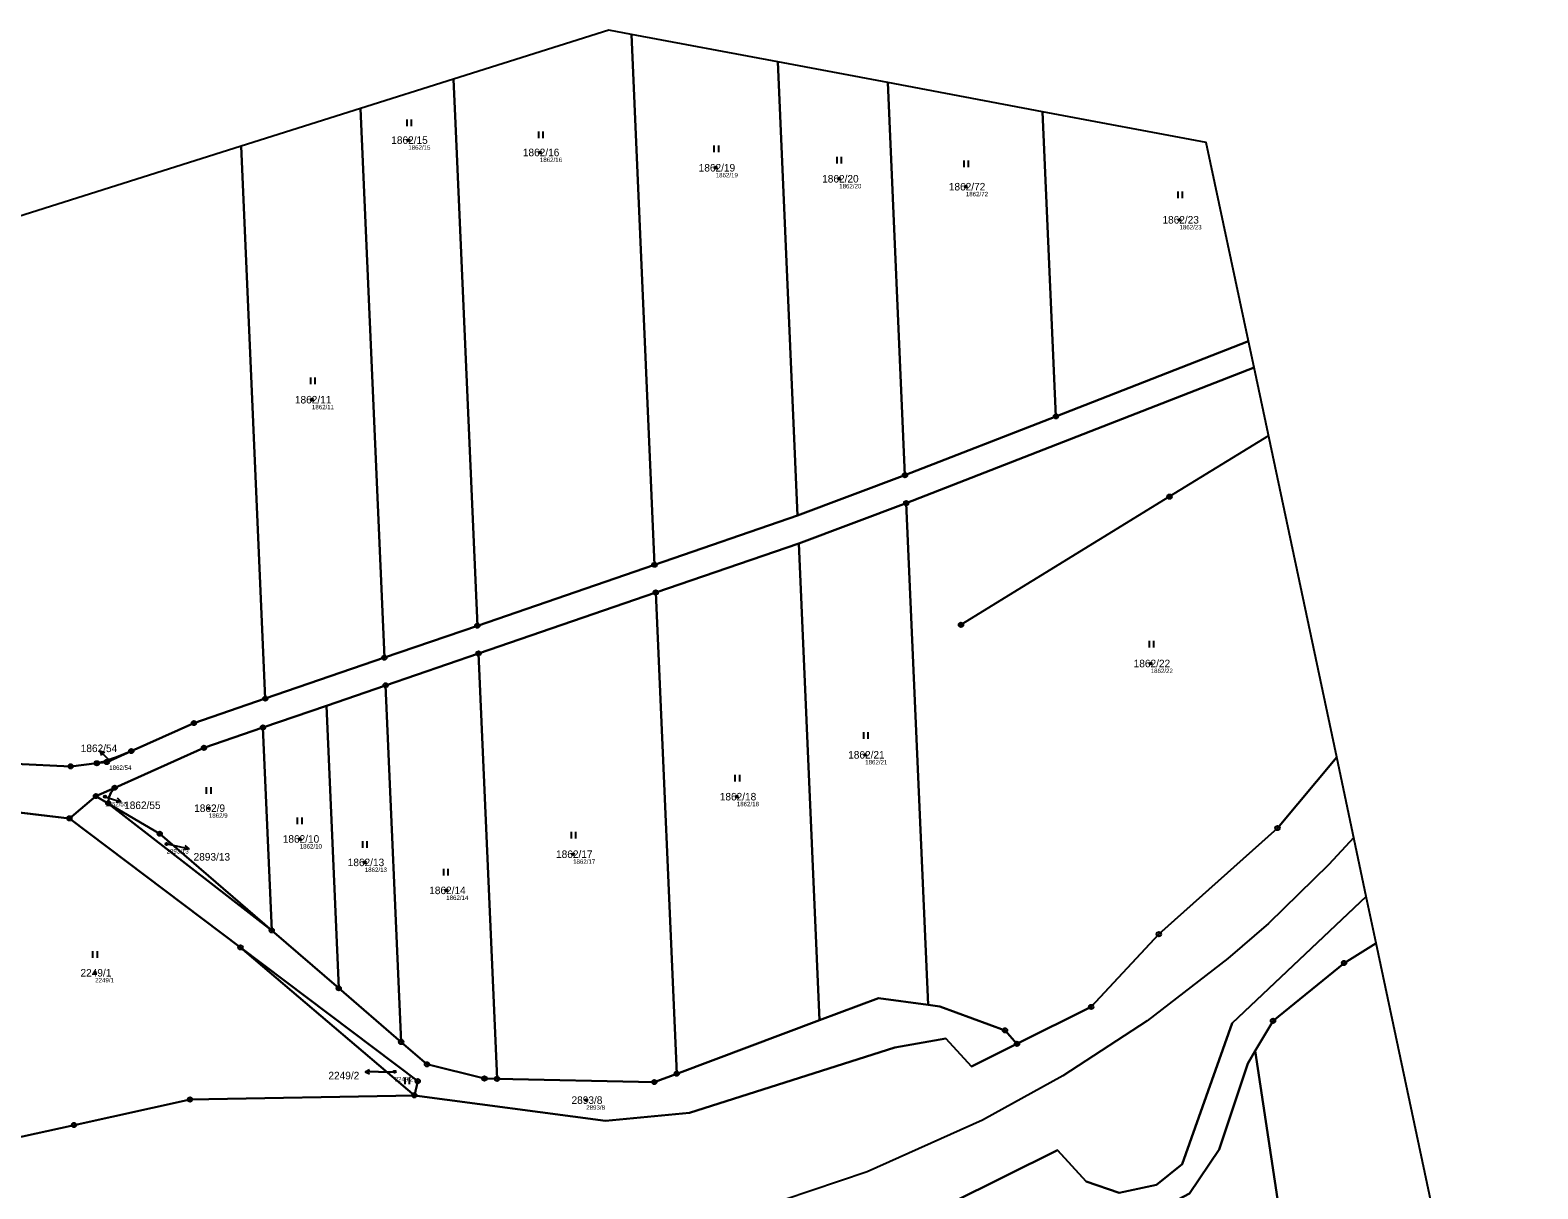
# Model space of a CAD drawing. Extents: x -758777 to -757896, y -1175225 to -1174486.
# Drawn here: x -758235.7 to -757895.9, y -1174746.8 to -1174485.6 of the extents above; entities that cross this region are included whole.
import ezdxf

# ---------------------------------------------------------------- set-up
doc = ezdxf.new("R2010")
doc.units = 0
for name, color, linetype in [('Definiční body', 7, 'Continuous'), ('Hranice parcel', 7, 'Continuous'), ('Parcelní čísla', 7, 'Continuous'), ('Polygon parcely', 7, 'Continuous'), ('Pop  PČ popisy', 7, 'Continuous'), ('Poz předměty', 7, 'Continuous'), ('Značky bodu BP', 7, 'Continuous'), ('Značky kultur', 7, 'Continuous')]:
    doc.layers.add(name, color=color, linetype=linetype)

msp = doc.modelspace()

# ---------------------------------------------------------------- linework, layer by layer
at = {"layer": 'Definiční body'}
for centre in [(-758150.45, -1174510.36), (-758120.8, -1174513.14), (-758081.18, -1174516.59), (-758053.36, -1174519.07), (-758024.82, -1174520.86), (-757976.69, -1174528.32), (-758172.16, -1174568.87), (-757983.17, -1174628.33), (-758217.83, -1174650.15), (-758047.5, -1174648.92), (-758218.78, -1174658.37), (-758076.43, -1174658.35), (-758195.39, -1174660.95), (-758174.9, -1174667.88), (-758204.92, -1174669.01), (-758113.32, -1174671.32), (-758160.26, -1174673.16), (-758141.9, -1174679.47), (-758221, -1174698.05), (-758153.53, -1174720.36), (-758110.36, -1174726.75)]:
    msp.add_circle(centre, 0.25, dxfattribs=at)
at = {"layer": 'Hranice parcel'}
for p, q in [((-758094.97, -1174606.08), (-758100.17, -1174486.52)), ((-758067.2, -1174492.73), (-758062.75, -1174595)), ((-758038.54, -1174585.88), (-758042.38, -1174497.4)), ((-758155.84, -1174627.01), (-758161.23, -1174503.26)), ((-758007.52, -1174503.96), (-758004.53, -1174572.62)), ((-758182.68, -1174636.24), (-758188.1, -1174511.75)), ((-757961.14, -1174555.7), (-758004.53, -1174572.62)), ((-758038.26, -1174592.18), (-757959.89, -1174561.63)), ((-758004.53, -1174572.62), (-758038.54, -1174585.88)), ((-758038.54, -1174585.88), (-758062.75, -1174595)), ((-758062.47, -1174601.25), (-758038.26, -1174592.18)), ((-758038.26, -1174592.18), (-758033.33, -1174705.3)), ((-758062.75, -1174595), (-758094.97, -1174606.08)), ((-758094.69, -1174612.33), (-758062.47, -1174601.25)), ((-758062.47, -1174601.25), (-758057.8, -1174708.75)), ((-758094.97, -1174606.08), (-758134.89, -1174619.81)), ((-758134.62, -1174626.06), (-758094.69, -1174612.33)), ((-758089.97, -1174720.79), (-758094.69, -1174612.33)), ((-758134.89, -1174619.81), (-758155.84, -1174627.01)), ((-758155.84, -1174627.01), (-758182.68, -1174636.24)), ((-758155.57, -1174633.26), (-758134.62, -1174626.06)), ((-758134.62, -1174626.06), (-758130.45, -1174721.94)), ((-758168.89, -1174637.84), (-758155.57, -1174633.26)), ((-758152.07, -1174713.65), (-758155.57, -1174633.26)), ((-758183.21, -1174642.76), (-758168.89, -1174637.84)), ((-758168.89, -1174637.84), (-758166.12, -1174701.53)), ((-758181.22, -1174688.49), (-758183.21, -1174642.76)), ((-758226.78, -1174663.24), (-758220.83, -1174658.22)), ((-758220.83, -1174658.22), (-758216.61, -1174656.33)), ((-758218.05, -1174659.86), (-758220.83, -1174658.22)), ((-758254.5, -1174659.99), (-758226.78, -1174663.24)), ((-758181.22, -1174688.49), (-758218.05, -1174659.86)), ((-758226.78, -1174663.24), (-758188.26, -1174692.33)), ((-758166.12, -1174701.53), (-758181.22, -1174688.49)), ((-758149.09, -1174725.67), (-758188.26, -1174692.33)), ((-758166.12, -1174701.53), (-758152.07, -1174713.65)), ((-758089.97, -1174720.79), (-758057.8, -1174708.75))]:
    msp.add_line(p, q, dxfattribs=at)
for points in [[(-758134.89, -1174619.81), (-758139.82, -1174506.61), (-758140.25, -1174496.64)], [(-758212.86, -1174648.07), (-758198.75, -1174641.76), (-758182.68, -1174636.24)], [(-758216.61, -1174656.33), (-758196.5, -1174647.34), (-758183.21, -1174642.76)], [(-758220.63, -1174650.81), (-758219.98, -1174650.66), (-758219, -1174650.41), (-758218.05, -1174650.11), (-758217.1, -1174649.77), (-758216.19, -1174649.41), (-758212.86, -1174648.07)], [(-758212.86, -1174648.07), (-758218.37, -1174650.54), (-758220.63, -1174650.81)], [(-758239.06, -1174650.93), (-758226.51, -1174651.52), (-758220.63, -1174650.81)], [(-758013.3, -1174714.07), (-757996.59, -1174705.74), (-757981.33, -1174689.35), (-757954.6, -1174665.43), (-757941.27, -1174649.42)], [(-758216.61, -1174656.33), (-758216.89, -1174656.64), (-758217.45, -1174657.45), (-758217.83, -1174658.36), (-758218.03, -1174659.32), (-758218.05, -1174659.86)], [(-758218.05, -1174659.86), (-758206.46, -1174666.7), (-758181.22, -1174688.49)], [(-757934.61, -1174680.85), (-757964.85, -1174709.42), (-757976.05, -1174741.17), (-757981.89, -1174745.86), (-757990.29, -1174747.68), (-757997.69, -1174745.08), (-758004.14, -1174738), (-758040.32, -1174755.99), (-758089.84, -1174768.68), (-758142.71, -1174770.26), (-758184.87, -1174772.83)], [(-757959.61, -1174715.65), (-757955.61, -1174708.87), (-757939.6, -1174695.85), (-757932.38, -1174691.39)], [(-758188.26, -1174692.33), (-758148.33, -1174722.48), (-758149.09, -1174725.67)], [(-758057.8, -1174708.75), (-758044.51, -1174703.78), (-758033.33, -1174705.3)], [(-758033.33, -1174705.3), (-758030.68, -1174705.66), (-758016, -1174711.02), (-758013.3, -1174714.07)], [(-758152.07, -1174713.65), (-758146.25, -1174718.68), (-758133.29, -1174721.88), (-758130.45, -1174721.94)], [(-758149.09, -1174725.67), (-758106.02, -1174731.44), (-758087.1, -1174729.64), (-758040.84, -1174714.91), (-758029.32, -1174712.86), (-758023.54, -1174719.17), (-758013.3, -1174714.07)], [(-757991.64, -1174752.6), (-757980.81, -1174751.2), (-757974.41, -1174747.76), (-757967.73, -1174737.89), (-757961.29, -1174718.5), (-757959.61, -1174715.65)], [(-757959.61, -1174715.65), (-757943.53, -1174822.15), (-757927.46, -1174928.58)], [(-758130.45, -1174721.94), (-758095.02, -1174722.68), (-758089.97, -1174720.79)], [(-758149.09, -1174725.67), (-758199.62, -1174726.6), (-758225.76, -1174732.36), (-758252.17, -1174738.18), (-758254.97, -1174739.34)]]:
    msp.add_lwpolyline(points, dxfattribs=at)
at = {"layer": 'Polygon parcely'}
for p, q in [((-758067.2, -1174492.73), (-758100.17, -1174486.52)), ((-758042.38, -1174497.4), (-758067.2, -1174492.73)), ((-758140.25, -1174496.64), (-758161.23, -1174503.26)), ((-758007.52, -1174503.96), (-758042.38, -1174497.4)), ((-758161.23, -1174503.26), (-758188.1, -1174511.75)), ((-757959.89, -1174561.63), (-757961.14, -1174555.7)), ((-757941.27, -1174649.42), (-757959.89, -1174561.63)), ((-757934.61, -1174680.85), (-757941.27, -1174649.42)), ((-757932.38, -1174691.39), (-757934.61, -1174680.85))]:
    msp.add_line(p, q, dxfattribs=at)
for points in [[(-758100.17, -1174486.52), (-758105.23, -1174485.57), (-758140.25, -1174496.64)], [(-758140.25, -1174496.64), (-758139.82, -1174506.61), (-758134.89, -1174619.81), (-758094.97, -1174606.08), (-758100.17, -1174486.52)], [(-758100.17, -1174486.52), (-758094.97, -1174606.08), (-758062.75, -1174595), (-758067.2, -1174492.73)], [(-758067.2, -1174492.73), (-758062.75, -1174595), (-758038.54, -1174585.88), (-758042.38, -1174497.4)], [(-758161.23, -1174503.26), (-758155.84, -1174627.01), (-758134.89, -1174619.81), (-758139.82, -1174506.61), (-758140.25, -1174496.64)], [(-758042.38, -1174497.4), (-758038.54, -1174585.88), (-758004.53, -1174572.62), (-758007.52, -1174503.96)], [(-758188.1, -1174511.75), (-758182.68, -1174636.24), (-758155.84, -1174627.01), (-758161.23, -1174503.26)], [(-757961.14, -1174555.7), (-757970.64, -1174510.89), (-758007.52, -1174503.96)], [(-758007.52, -1174503.96), (-758004.53, -1174572.62), (-757961.14, -1174555.7)], [(-758188.1, -1174511.75), (-758257.72, -1174533.75), (-758263.47, -1174537.13)], [(-758263.47, -1174537.13), (-758261.99, -1174564.85), (-758261.59, -1174594.45), (-758261.42, -1174607.5), (-758261.03, -1174649.91), (-758247.67, -1174650.53), (-758245.32, -1174650.56), (-758243.31, -1174650.57), (-758242.31, -1174650.6), (-758241.31, -1174650.66), (-758240.32, -1174650.75), (-758239.33, -1174650.89), (-758239.06, -1174650.93), (-758226.51, -1174651.52), (-758220.63, -1174650.81), (-758219.98, -1174650.66), (-758219, -1174650.41), (-758218.05, -1174650.11), (-758217.1, -1174649.77), (-758216.19, -1174649.41), (-758212.86, -1174648.07), (-758198.75, -1174641.76), (-758182.68, -1174636.24), (-758188.1, -1174511.75)], [(-757961.14, -1174555.7), (-758004.53, -1174572.62), (-758038.54, -1174585.88), (-758062.75, -1174595), (-758094.97, -1174606.08), (-758134.89, -1174619.81), (-758155.84, -1174627.01), (-758182.68, -1174636.24), (-758198.75, -1174641.76), (-758212.86, -1174648.07), (-758218.37, -1174650.54), (-758220.63, -1174650.81), (-758226.51, -1174651.52), (-758239.06, -1174650.93)], [(-758254.5, -1174659.99), (-758226.78, -1174663.24), (-758220.83, -1174658.22), (-758216.61, -1174656.33), (-758196.5, -1174647.34), (-758183.21, -1174642.76), (-758168.89, -1174637.84), (-758155.57, -1174633.26), (-758134.62, -1174626.06), (-758094.69, -1174612.33), (-758062.47, -1174601.25), (-758038.26, -1174592.18), (-757959.89, -1174561.63)], [(-757959.89, -1174561.63), (-758038.26, -1174592.18), (-758033.33, -1174705.3), (-758030.68, -1174705.66), (-758016, -1174711.02), (-758013.3, -1174714.07), (-757996.59, -1174705.74), (-757981.33, -1174689.35), (-757954.6, -1174665.43), (-757941.27, -1174649.42)], [(-757941.27, -1174649.42), (-757954.6, -1174665.43), (-757981.33, -1174689.35), (-757996.59, -1174705.74)], [(-758267.96, -1174782.93), (-758224.96, -1174775.27), (-758184.87, -1174772.83), (-758142.71, -1174770.26), (-758089.84, -1174768.68), (-758040.32, -1174755.99), (-758004.14, -1174738), (-757997.69, -1174745.08), (-757990.29, -1174747.68), (-757981.89, -1174745.86), (-757976.05, -1174741.17), (-757964.85, -1174709.42), (-757934.61, -1174680.85)], [(-757934.61, -1174680.85), (-757964.85, -1174709.42), (-757976.05, -1174741.17), (-757981.89, -1174745.86), (-757990.29, -1174747.68), (-757997.69, -1174745.08), (-758004.14, -1174738), (-758040.32, -1174755.99)], [(-757974.41, -1174747.76), (-757967.73, -1174737.89), (-757961.29, -1174718.5), (-757959.61, -1174715.65), (-757955.61, -1174708.87), (-757939.6, -1174695.85), (-757932.38, -1174691.39)], [(-757932.38, -1174691.39), (-757939.6, -1174695.85), (-757955.61, -1174708.87), (-757959.61, -1174715.65), (-757943.53, -1174822.15), (-757927.46, -1174928.58), (-757896.24, -1174941.82)], [(-757896.24, -1174941.82), (-757895.94, -1174848.13), (-757918.79, -1174755.48), (-757932.38, -1174691.39)], [(-757996.59, -1174705.74), (-758013.3, -1174714.07), (-758023.54, -1174719.17), (-758029.32, -1174712.86), (-758040.84, -1174714.91), (-758087.1, -1174729.64), (-758106.02, -1174731.44), (-758149.09, -1174725.67), (-758199.62, -1174726.6), (-758225.76, -1174732.36), (-758252.17, -1174738.18), (-758254.97, -1174739.34)]]:
    msp.add_lwpolyline(points, dxfattribs=at)
for points in [[(-758057.8, -1174708.75), (-758044.51, -1174703.78), (-758033.33, -1174705.3), (-758038.26, -1174592.18), (-758062.47, -1174601.25)], [(-758057.8, -1174708.75), (-758062.47, -1174601.25), (-758094.69, -1174612.33), (-758089.97, -1174720.79)], [(-758089.97, -1174720.79), (-758094.69, -1174612.33), (-758134.62, -1174626.06), (-758130.45, -1174721.94), (-758095.02, -1174722.68)], [(-758133.29, -1174721.88), (-758130.45, -1174721.94), (-758134.62, -1174626.06), (-758155.57, -1174633.26), (-758152.07, -1174713.65), (-758146.25, -1174718.68)], [(-758168.89, -1174637.84), (-758166.12, -1174701.53), (-758152.07, -1174713.65), (-758155.57, -1174633.26)], [(-758168.89, -1174637.84), (-758183.21, -1174642.76), (-758181.22, -1174688.49), (-758166.12, -1174701.53)], [(-758218.05, -1174659.86), (-758206.46, -1174666.7), (-758181.22, -1174688.49), (-758183.21, -1174642.76), (-758196.5, -1174647.34), (-758216.61, -1174656.33), (-758216.89, -1174656.64), (-758217.45, -1174657.45), (-758217.83, -1174658.36), (-758218.03, -1174659.32)], [(-758212.86, -1174648.07), (-758216.19, -1174649.41), (-758217.1, -1174649.77), (-758218.05, -1174650.11), (-758219, -1174650.41), (-758219.98, -1174650.66), (-758220.63, -1174650.81), (-758218.37, -1174650.54)], [(-758181.22, -1174688.49), (-758218.05, -1174659.86), (-758220.83, -1174658.22), (-758226.78, -1174663.24), (-758188.26, -1174692.33), (-758148.33, -1174722.48), (-758149.09, -1174725.67), (-758106.02, -1174731.44), (-758087.1, -1174729.64), (-758040.84, -1174714.91), (-758029.32, -1174712.86), (-758023.54, -1174719.17), (-758013.3, -1174714.07), (-758016, -1174711.02), (-758030.68, -1174705.66), (-758033.33, -1174705.3), (-758044.51, -1174703.78), (-758057.8, -1174708.75), (-758089.97, -1174720.79), (-758095.02, -1174722.68), (-758130.45, -1174721.94), (-758133.29, -1174721.88), (-758146.25, -1174718.68), (-758152.07, -1174713.65), (-758166.12, -1174701.53)], [(-758216.61, -1174656.33), (-758220.83, -1174658.22), (-758218.05, -1174659.86), (-758218.03, -1174659.32), (-758217.83, -1174658.36), (-758217.45, -1174657.45), (-758216.89, -1174656.64)], [(-758149.09, -1174725.67), (-758188.26, -1174692.33), (-758226.78, -1174663.24), (-758254.5, -1174659.99), (-758254.45, -1174715.89), (-758254.97, -1174739.34), (-758252.17, -1174738.18), (-758225.76, -1174732.36), (-758199.62, -1174726.6)], [(-758181.22, -1174688.49), (-758206.46, -1174666.7), (-758218.05, -1174659.86)], [(-758149.09, -1174725.67), (-758148.33, -1174722.48), (-758188.26, -1174692.33)], [(-757927.46, -1174928.58), (-757943.53, -1174822.15), (-757959.61, -1174715.65), (-757961.29, -1174718.5), (-757967.73, -1174737.89), (-757974.41, -1174747.76), (-757980.81, -1174751.2), (-757991.64, -1174752.6), (-757966.21, -1174921.06), (-757955.71, -1174920.78), (-757947.16, -1174921.89), (-757938.71, -1174923.81)]]:
    msp.add_lwpolyline(points, close=True, dxfattribs=at)
at = {"layer": 'Pop  PČ popisy'}
for p, q in [((-758217.83, -1174650.15), (-758219.92, -1174647.99)), ((-758219.92, -1174647.99), (-758218.86, -1174648.36)), ((-758219.92, -1174647.99), (-758219.58, -1174649.06)), ((-758218.78, -1174658.37), (-758218.05, -1174658.6)), ((-758218.05, -1174658.6), (-758215.18, -1174659.48)), ((-758215.18, -1174659.48), (-758216.28, -1174659.66)), ((-758215.18, -1174659.48), (-758215.99, -1174658.71)), ((-758204.92, -1174669.01), (-758202.79, -1174669.45)), ((-758202.79, -1174669.45), (-758199.85, -1174670.07)), ((-758199.85, -1174670.07), (-758200.94, -1174670.36)), ((-758199.85, -1174670.07), (-758200.73, -1174669.38)), ((-758160.19, -1174720.36), (-758159.19, -1174719.86)), ((-758157.19, -1174720.36), (-758160.19, -1174720.36)), ((-758160.19, -1174720.36), (-758159.19, -1174720.86)), ((-758157.19, -1174720.36), (-758153.53, -1174720.36))]:
    msp.add_line(p, q, dxfattribs=at)
at = {"layer": 'Poz předměty'}
for p, q in [((-757956.63, -1174576.98), (-757978.95, -1174590.72)), ((-757978.95, -1174590.72), (-758025.92, -1174619.62)), ((-757937.43, -1174667.53), (-757943, -1174673.62)), ((-757943, -1174673.62), (-757956.66, -1174686.9)), ((-757956.66, -1174686.9), (-757965.77, -1174694.81)), ((-757965.77, -1174694.81), (-757983.98, -1174708.88)), ((-757983.98, -1174708.88), (-758002.99, -1174721.31)), ((-758002.99, -1174721.31), (-758021.05, -1174731.29)), ((-758021.05, -1174731.29), (-758047.05, -1174742.88)), ((-758047.05, -1174742.88), (-758072, -1174751.3))]:
    msp.add_line(p, q, dxfattribs=at)
for centre, radius in [((-757978.95, -1174590.72), 0.5), ((-757978.95, -1174590.72), 0.4), ((-757978.95, -1174590.72), 0.3), ((-757978.95, -1174590.72), 0.2), ((-757978.95, -1174590.72), 0.1), ((-758025.92, -1174619.62), 0.5), ((-758025.92, -1174619.62), 0.4), ((-758025.92, -1174619.62), 0.3), ((-758025.92, -1174619.62), 0.2), ((-758025.92, -1174619.62), 0.1)]:
    msp.add_circle(centre, radius, dxfattribs=at)
at = {"layer": 'Značky bodu BP'}
for centre, radius in [((-758004.53, -1174572.62), 0.5), ((-758004.53, -1174572.62), 0.0303), ((-758038.54, -1174585.88), 0.5), ((-758038.54, -1174585.88), 0.0303), ((-758038.26, -1174592.18), 0.5), ((-758038.26, -1174592.18), 0.0303), ((-758094.97, -1174606.08), 0.5), ((-758094.97, -1174606.08), 0.0303), ((-758094.69, -1174612.33), 0.5), ((-758094.69, -1174612.33), 0.0303), ((-758134.89, -1174619.81), 0.5), ((-758134.89, -1174619.81), 0.0303), ((-758155.84, -1174627.01), 0.5), ((-758155.84, -1174627.01), 0.0303), ((-758134.62, -1174626.06), 0.5), ((-758134.62, -1174626.06), 0.0303), ((-758155.57, -1174633.26), 0.5), ((-758155.57, -1174633.26), 0.0303), ((-758182.68, -1174636.24), 0.5), ((-758182.68, -1174636.24), 0.0303), ((-758198.75, -1174641.76), 0.5), ((-758198.75, -1174641.76), 0.0303), ((-758183.21, -1174642.76), 0.5), ((-758183.21, -1174642.76), 0.0303), ((-758212.86, -1174648.07), 0.5), ((-758212.86, -1174648.07), 0.0303), ((-758196.5, -1174647.34), 0.5), ((-758196.5, -1174647.34), 0.0303), ((-758226.51, -1174651.52), 0.5), ((-758226.51, -1174651.52), 0.0303), ((-758220.63, -1174650.81), 0.5), ((-758220.63, -1174650.81), 0.0303), ((-758218.37, -1174650.54), 0.5), ((-758218.37, -1174650.54), 0.0303), ((-758220.83, -1174658.22), 0.5), ((-758220.83, -1174658.22), 0.0303), ((-758216.61, -1174656.33), 0.5), ((-758216.61, -1174656.33), 0.0303), ((-758218.05, -1174659.86), 0.5), ((-758218.05, -1174659.86), 0.0303), ((-758226.78, -1174663.24), 0.5), ((-758226.78, -1174663.24), 0.0303), ((-757954.6, -1174665.43), 0.5), ((-758206.46, -1174666.7), 0.5), ((-758206.46, -1174666.7), 0.0303), ((-757954.6, -1174665.43), 0.0303), ((-758181.22, -1174688.49), 0.5), ((-758181.22, -1174688.49), 0.0303), ((-757981.33, -1174689.35), 0.5), ((-758188.26, -1174692.33), 0.5), ((-758188.26, -1174692.33), 0.0303), ((-757981.33, -1174689.35), 0.0303), ((-757939.6, -1174695.85), 0.5), ((-757939.6, -1174695.85), 0.0303), ((-758166.12, -1174701.53), 0.5), ((-758166.12, -1174701.53), 0.0303), ((-757996.59, -1174705.74), 0.5), ((-757996.59, -1174705.74), 0.0303), ((-757955.61, -1174708.87), 0.5), ((-757955.61, -1174708.87), 0.0303), ((-758016, -1174711.02), 0.5), ((-758016, -1174711.02), 0.0303), ((-758152.07, -1174713.65), 0.5), ((-758152.07, -1174713.65), 0.0303), ((-758013.3, -1174714.07), 0.5), ((-758013.3, -1174714.07), 0.0303), ((-758146.25, -1174718.68), 0.5), ((-758146.25, -1174718.68), 0.0303), ((-758148.33, -1174722.48), 0.5), ((-758148.33, -1174722.48), 0.0303), ((-758133.29, -1174721.88), 0.5), ((-758133.29, -1174721.88), 0.0303), ((-758130.45, -1174721.94), 0.5), ((-758130.45, -1174721.94), 0.0303), ((-758095.02, -1174722.68), 0.5), ((-758095.02, -1174722.68), 0.0303), ((-758089.97, -1174720.79), 0.5), ((-758089.97, -1174720.79), 0.0303), ((-758199.62, -1174726.6), 0.5), ((-758149.09, -1174725.67), 0.5), ((-758149.09, -1174725.67), 0.0303), ((-758199.62, -1174726.6), 0.0303), ((-758225.76, -1174732.36), 0.5), ((-758225.76, -1174732.36), 0.0303)]:
    msp.add_circle(centre, radius, dxfattribs=at)
at = {"layer": 'Značky kultur'}
for p, q in [((-758150.72, -1174507.25), (-758150.72, -1174505.75)), ((-758149.72, -1174507.25), (-758149.72, -1174505.75)), ((-758121.07, -1174509.92), (-758121.07, -1174508.42)), ((-758120.07, -1174509.92), (-758120.07, -1174508.42)), ((-758081.51, -1174513.04), (-758081.51, -1174511.54)), ((-758080.51, -1174513.04), (-758080.51, -1174511.54)), ((-758053.82, -1174515.65), (-758053.82, -1174514.15)), ((-758052.82, -1174515.65), (-758052.82, -1174514.15)), ((-758025.23, -1174516.44), (-758025.23, -1174514.94)), ((-758024.23, -1174516.44), (-758024.23, -1174514.94)), ((-757977, -1174523.41), (-757977, -1174521.91)), ((-757976, -1174523.41), (-757976, -1174521.91)), ((-758172.45, -1174565.38), (-758172.45, -1174563.88)), ((-758171.45, -1174565.38), (-758171.45, -1174563.88)), ((-757983.46, -1174624.74), (-757983.46, -1174623.24)), ((-757982.46, -1174624.74), (-757982.46, -1174623.24)), ((-758047.83, -1174645.34), (-758047.83, -1174643.84)), ((-758046.83, -1174645.34), (-758046.83, -1174643.84)), ((-758076.77, -1174654.94), (-758076.77, -1174653.44)), ((-758075.77, -1174654.94), (-758075.77, -1174653.44)), ((-758195.9, -1174657.7), (-758195.9, -1174656.2)), ((-758194.9, -1174657.7), (-758194.9, -1174656.2)), ((-758175.38, -1174664.57), (-758175.38, -1174663.07)), ((-758174.38, -1174664.57), (-758174.38, -1174663.07)), ((-758160.73, -1174669.88), (-758160.73, -1174668.38)), ((-758159.73, -1174669.88), (-758159.73, -1174668.38)), ((-758113.67, -1174667.8), (-758113.67, -1174666.3)), ((-758112.67, -1174667.8), (-758112.67, -1174666.3)), ((-758142.48, -1174676.09), (-758142.48, -1174674.59)), ((-758141.48, -1174676.09), (-758141.48, -1174674.59)), ((-758221.5, -1174694.66), (-758221.5, -1174693.16)), ((-758220.5, -1174694.66), (-758220.5, -1174693.16)), ((-758151.17, -1174723.18), (-758151.17, -1174721.68)), ((-758150.17, -1174723.18), (-758150.17, -1174721.68))]:
    msp.add_line(p, q, dxfattribs=at)

# ---------------------------------------------------------------- texts
at = {"layer": 'Definiční body'}
for s, p in [('1862/15', (-758150.45, -1174512.52)), ('1862/16', (-758120.8, -1174515.3)), ('1862/19', (-758081.18, -1174518.75)), ('1862/20', (-758053.36, -1174521.23)), ('1862/72', (-758024.82, -1174523.02)), ('1862/23', (-757976.69, -1174530.48)), ('1862/11', (-758172.16, -1174571.03)), ('1862/22', (-757983.17, -1174630.49)), ('1862/54', (-758217.83, -1174652.31)), ('1862/21', (-758047.5, -1174651.08)), ('1862/55', (-758218.78, -1174660.53)), ('1862/18', (-758076.43, -1174660.51)), ('1862/9', (-758195.39, -1174663.11)), ('2893/13', (-758204.92, -1174671.17)), ('1862/10', (-758174.9, -1174670.04)), ('1862/13', (-758160.26, -1174675.32)), ('1862/17', (-758113.32, -1174673.48)), ('1862/14', (-758141.9, -1174681.63)), ('2249/1', (-758221, -1174700.21)), ('2249/2', (-758153.53, -1174722.52)), ('2893/8', (-758110.36, -1174728.91))]:
    msp.add_text(s, height=1, dxfattribs=at).set_placement(p)
at = {"layer": 'Parcelní čísla'}
for s, p in [('1862/15', (-758154.29, -1174511.21)), ('1862/16', (-758124.64, -1174513.99)), ('1862/19', (-758085.02, -1174517.44)), ('1862/20', (-758057.2, -1174519.92)), ('1862/72', (-758028.66, -1174521.71)), ('1862/23', (-757980.53, -1174529.17)), ('1862/11', (-758176, -1174569.72)), ('1862/22', (-757987.01, -1174629.18)), ('1862/54', (-758224.26, -1174648.3)), ('1862/21', (-758051.34, -1174649.77)), ('1862/18', (-758080.27, -1174659.2)), ('1862/55', (-758214.48, -1174661.14)), ('1862/9', (-758198.7, -1174661.8)), ('1862/10', (-758178.74, -1174668.73)), ('2893/13', (-758198.83, -1174672.76)), ('1862/17', (-758117.16, -1174672.17)), ('1862/13', (-758164.1, -1174674.01)), ('1862/14', (-758145.74, -1174680.32)), ('2249/1', (-758224.31, -1174698.9)), ('2249/2', (-758168.45, -1174722.06)), ('2893/8', (-758113.67, -1174727.6))]:
    msp.add_text(s, height=1.7, dxfattribs=at).set_placement(p)

doc.saveas('drawing.dxf')
